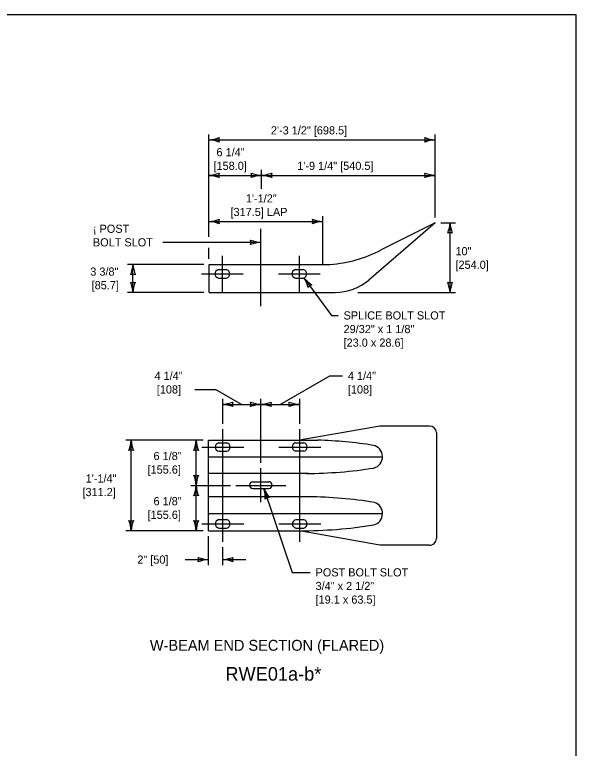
# Model space of a CAD drawing. Extents: x 49991.4 to 50021, y 49987.6 to 50011.4.
# Drawn here: x 50004.48 to 50008.61, y 50005.87 to 50011.26 of the extents above; entities that cross this region are included whole.
import ezdxf

# ---------------------------------------------------------------- set-up
doc = ezdxf.new("R2010")
doc.units = 0
for name, color, linetype in [('Level 1', 7, 'Continuous'), ('Level 2', 7, 'Continuous'), ('Level 3', 7, 'Continuous'), ('Level 5', 7, 'Continuous')]:
    doc.layers.add(name, color=color, linetype=linetype)

msp = doc.modelspace()

# ---------------------------------------------------------------- linework, layer by layer
at = {"layer": 'Level 1'}
for p, q in [((50007.577, 50009.7319), (50007.0892, 50009.3105)), ((50007.577, 50009.7319), (50007.1778, 50009.5325)), ((50005.9132, 50009.2185), (50005.9132, 50009.4265)), ((50005.9132, 50009.4265), (50006.8026, 50009.4265)), ((50005.9814, 50009.3881), (50006.0394, 50009.3881)), ((50006.548, 50009.3881), (50006.606, 50009.3881)), ((50005.9814, 50009.3255), (50006.0393, 50009.3255)), ((50006.5481, 50009.3255), (50006.606, 50009.3255)), ((50005.9132, 50009.2185), (50006.8398, 50009.2185)), ((50007.1678, 50008.2372), (50006.5772, 50008.1336)), ((50007.5344, 50008.2372), (50007.1678, 50008.2372)), ((50007.5858, 50008.1895), (50007.5858, 50007.4106)), ((50005.909, 50007.4669), (50005.909, 50008.1336)), ((50005.909, 50008.1336), (50006.7125, 50008.1336)), ((50005.9839, 50008.1141), (50006.0422, 50008.1141)), ((50006.5504, 50008.1144), (50006.609, 50008.1144)), ((50005.909, 50008.0104), (50007.1888, 50008.0104)), ((50005.9838, 50008.0516), (50006.0423, 50008.0516)), ((50006.5506, 50008.0519), (50006.5506, 50008.0519)), ((50006.6088, 50008.0519), (50006.5506, 50008.0519)), ((50006.644, 50007.8874), (50005.909, 50007.8874)), ((50006.2335, 50007.8276), (50006.3515, 50007.8276)), ((50006.2348, 50007.7776), (50006.3527, 50007.7776)), ((50006.644, 50007.7166), (50005.909, 50007.7166)), ((50005.909, 50007.5944), (50007.1888, 50007.5944)), ((50005.9839, 50007.5489), (50006.0422, 50007.5489)), ((50006.6087, 50007.5485), (50006.5507, 50007.5485)), ((50005.9838, 50007.4864), (50006.0423, 50007.4864)), ((50006.5507, 50007.4859), (50006.6087, 50007.4859)), ((50005.909, 50007.4669), (50006.5772, 50007.4669)), ((50007.1678, 50007.3609), (50006.5768, 50007.4669)), ((50007.5313, 50007.3609), (50007.1678, 50007.3609))]:
    msp.add_line(p, q, dxfattribs=at)
msp.add_lwpolyline([(50008.6146, 50011.2628), (50000.3356, 50011.2628), (50000.3356, 50000.0624), (50008.6146, 50000.0624)], close=True, dxfattribs=at)
for centre, radius, start, end in [((50006.7393, 50010.3672), 0.9429, 273.8489, 297.7135), ((50005.9883, 50009.3568), 0.0321, 102.4385, 257.5922), ((50006.0324, 50009.3568), 0.0321, 282.411, 77.5583), ((50006.555, 50009.3568), 0.0321, 102.4385, 257.5922), ((50006.5991, 50009.3568), 0.0321, 282.411, 77.5583), ((50006.83, 50009.6289), 0.4105, 271.3668, 309.1473), ((50007.5354, 50008.1867), 0.0505, 3.1941, 91.1135), ((50006.5981, 50004.7284), 3.4071, 81.1729, 88.076), ((50005.991, 50008.0828), 0.0321, 102.7122, 257.0492), ((50006.0351, 50008.0828), 0.0321, 282.9538, 77.2847), ((50006.5576, 50008.0832), 0.0321, 102.9802, 257.2893), ((50006.6018, 50008.0832), 0.0321, 282.6853, 77.0167), ((50007.103, 50008.0113), 0.0858, 285.168, 77.951), ((50006.5969, 50011.2943), 3.4071, 270.5497, 278.925), ((50006.2348, 50007.8026), 0.025, 93.1278, 270.0049), ((50006.3515, 50007.8026), 0.025, 272.7801, 89.9976), ((50006.6008, 50004.3098), 3.4071, 81.0853, 89.273), ((50007.1024, 50007.5935), 0.0864, 285.0365, 72.2425), ((50005.991, 50007.5176), 0.0321, 102.6822, 257.0198), ((50006.0351, 50007.5176), 0.0321, 282.9833, 77.3147), ((50006.5576, 50007.5172), 0.0321, 102.4078, 257.5615), ((50006.6018, 50007.5172), 0.0321, 282.4417, 77.589), ((50006.5842, 50010.874), 3.4071, 269.8825, 279.1301), ((50007.5345, 50007.4121), 0.0513, 266.5051, 358.2722)]:
    msp.add_arc(centre, radius, start, end, dxfattribs=at)
at = {"layer": 'Level 3'}
for p, q in [((50005.9104, 50009.6284), (50005.9104, 50010.3821)), ((50005.9104, 50010.3421), (50007.577, 50010.3421)), ((50007.577, 50009.7719), (50007.577, 50010.3821)), ((50006.298, 50009.9816), (50006.298, 50010.1211)), ((50005.9104, 50010.0811), (50006.298, 50010.0811)), ((50006.298, 50010.0811), (50007.577, 50010.0811)), ((50005.9104, 50009.7416), (50006.7506, 50009.7416)), ((50006.7506, 50009.4265), (50006.7506, 50009.7816)), ((50007.617, 50009.7319), (50007.7254, 50009.7319)), ((50007.6854, 50009.2185), (50007.6854, 50009.7319)), ((50005.5724, 50009.5884), (50006.2937, 50009.5884)), ((50005.9104, 50009.4665), (50005.9104, 50009.5484)), ((50005.8732, 50009.4265), (50005.3127, 50009.4265)), ((50005.3527, 50009.2185), (50005.3527, 50009.4265)), ((50006.611, 50009.327), (50006.8124, 50009.0508)), ((50005.8732, 50009.2185), (50005.3127, 50009.2185)), ((50007.007, 50009.2185), (50007.7254, 50009.2185)), ((50006.8124, 50009.0508), (50006.8621, 50009.0508)), ((50006.4353, 50008.3968), (50006.8007, 50008.6064)), ((50006.8007, 50008.6064), (50006.8938, 50008.6064)), ((50005.8079, 50008.5064), (50005.961, 50008.5064)), ((50006.1521, 50008.3968), (50005.961, 50008.5064)), ((50006.0104, 50008.4368), (50006.0104, 50008.2544)), ((50006.0104, 50008.3968), (50006.2937, 50008.3968)), ((50006.2937, 50007.9676), (50006.2937, 50008.4368)), ((50006.2937, 50008.3968), (50006.577, 50008.3968)), ((50006.577, 50008.4368), (50006.577, 50008.2544)), ((50005.869, 50008.1336), (50005.2991, 50008.1336)), ((50005.3391, 50007.4675), (50005.3391, 50008.1336)), ((50005.818, 50007.8002), (50005.818, 50008.1336)), ((50005.778, 50007.8002), (50006.0699, 50007.8002)), ((50005.818, 50007.4669), (50005.818, 50007.8002)), ((50006.3167, 50007.7776), (50006.5229, 50007.1611)), ((50005.869, 50007.4669), (50005.2991, 50007.4669)), ((50005.909, 50007.2147), (50005.909, 50007.4269)), ((50006.0104, 50007.3464), (50006.0104, 50007.2147)), ((50005.7356, 50007.2547), (50005.909, 50007.2547)), ((50006.0104, 50007.2547), (50006.1838, 50007.2547)), ((50006.5229, 50007.1611), (50006.656, 50007.1611))]:
    msp.add_line(p, q, dxfattribs=at)
for centre, radius, start, end in [((50005.8989, 50010.5749), 0.233, 272.8273, 292.0772), ((50005.9012, 50010.12), 0.2223, 67.456, 87.6395), ((50006.0386, 50010.3421), 0.0548, 162.1388, 197.8612), ((50007.5862, 50010.5643), 0.2223, 247.456, 267.6395), ((50007.4488, 50010.3421), 0.0548, 342.1388, 17.8612), ((50007.5885, 50010.1094), 0.233, 92.8273, 112.0772), ((50005.8989, 50010.3139), 0.233, 272.8273, 292.0772), ((50005.9012, 50009.859), 0.2223, 67.456, 87.6395), ((50006.0386, 50010.0811), 0.0548, 162.1388, 197.8612), ((50006.3072, 50010.3033), 0.2223, 247.456, 267.6395), ((50006.1698, 50010.0811), 0.0548, 342.1388, 17.8612), ((50006.3095, 50009.8484), 0.233, 92.8273, 112.0772), ((50006.2865, 50010.3139), 0.233, 272.8273, 292.0772), ((50006.2888, 50009.859), 0.2223, 67.456, 87.6395), ((50006.4262, 50010.0811), 0.0548, 162.1388, 197.8612), ((50007.5862, 50010.3033), 0.2223, 247.456, 267.6395), ((50007.4488, 50010.0811), 0.0548, 342.1388, 17.8612), ((50007.5885, 50009.8484), 0.233, 92.8273, 112.0772), ((50005.8989, 50009.9744), 0.233, 272.8273, 292.0772), ((50005.9012, 50009.5195), 0.2223, 67.456, 87.6395), ((50006.0386, 50009.7416), 0.0548, 162.1388, 197.8612), ((50006.7598, 50009.9638), 0.2223, 247.456, 267.6395), ((50006.6224, 50009.7416), 0.0548, 342.1388, 17.8612), ((50006.7621, 50009.5089), 0.233, 92.8273, 112.0772), ((50007.4633, 50009.7411), 0.2223, 337.456, 357.6395), ((50007.9181, 50009.7434), 0.233, 182.8273, 202.0772), ((50007.6854, 50009.6037), 0.0548, 72.1388, 107.8612), ((50006.3029, 50009.8105), 0.2223, 247.456, 267.6395), ((50006.1655, 50009.5884), 0.0548, 342.1388, 17.8612), ((50006.3052, 50009.3557), 0.233, 92.8273, 112.0772), ((50005.1306, 50009.4357), 0.2223, 337.456, 357.6395), ((50005.5854, 50009.438), 0.233, 182.8273, 202.0772), ((50005.3527, 50009.2983), 0.0548, 72.1388, 107.8612), ((50006.4261, 50009.2036), 0.2223, 13.554, 33.7375), ((50006.7922, 50009.4734), 0.233, 218.9253, 238.1751), ((50005.3527, 50009.3467), 0.0548, 252.1388, 287.8612), ((50005.12, 50009.207), 0.233, 2.8273, 22.0772), ((50005.5748, 50009.2093), 0.2223, 157.456, 177.6395), ((50006.6865, 50009.2234), 0.0548, 108.2368, 143.9591), ((50007.6854, 50009.3467), 0.0548, 252.1388, 287.8612), ((50007.4527, 50009.207), 0.233, 2.8273, 22.0772), ((50007.9075, 50009.2093), 0.2223, 157.456, 177.6395), ((50005.9989, 50008.6295), 0.233, 272.8273, 292.0772), ((50006.0012, 50008.1747), 0.2223, 67.456, 87.6395), ((50006.1386, 50008.3968), 0.0548, 162.1388, 197.8612), ((50006.3029, 50008.6189), 0.2223, 247.456, 267.6395), ((50006.1655, 50008.3968), 0.0548, 342.1388, 17.8612), ((50006.3052, 50008.1641), 0.233, 92.8273, 112.0772), ((50006.2822, 50008.6295), 0.233, 272.8273, 292.0772), ((50006.2845, 50008.1747), 0.2223, 67.456, 87.6395), ((50006.4219, 50008.3968), 0.0548, 162.1388, 197.8612), ((50006.5862, 50008.6189), 0.2223, 247.456, 267.6395), ((50006.4488, 50008.3968), 0.0548, 342.1388, 17.8612), ((50006.5885, 50008.1641), 0.233, 92.8273, 112.0772), ((50005.117, 50008.1428), 0.2223, 337.456, 357.6395), ((50005.5718, 50008.1451), 0.233, 182.8273, 202.0772), ((50005.5959, 50008.1428), 0.2223, 337.456, 357.6395), ((50006.0507, 50008.1451), 0.233, 182.8273, 202.0772), ((50005.3391, 50008.0054), 0.0548, 72.1388, 107.8612), ((50005.818, 50008.0054), 0.0548, 72.1388, 107.8612), ((50005.818, 50007.9284), 0.0548, 252.1388, 287.8612), ((50005.5853, 50007.7887), 0.233, 2.8273, 22.0772), ((50006.0401, 50007.791), 0.2223, 157.456, 177.6395), ((50005.5959, 50007.8094), 0.2223, 337.456, 357.6395), ((50006.0507, 50007.8117), 0.233, 182.8273, 202.0772), ((50006.1031, 50007.7159), 0.2223, 355.9453, 16.1288), ((50006.5338, 50007.8623), 0.233, 201.3166, 220.5665), ((50005.818, 50007.672), 0.0548, 72.1388, 107.8612), ((50006.3574, 50007.656), 0.0548, 90.6281, 126.3505), ((50005.3391, 50007.5951), 0.0548, 252.1388, 287.8612), ((50005.1064, 50007.4554), 0.233, 2.8273, 22.0772), ((50005.5612, 50007.4577), 0.2223, 157.456, 177.6395), ((50005.818, 50007.5951), 0.0548, 252.1388, 287.8612), ((50005.5853, 50007.4554), 0.233, 2.8273, 22.0772), ((50006.0401, 50007.4577), 0.2223, 157.456, 177.6395), ((50005.9182, 50007.4768), 0.2223, 247.456, 267.6395), ((50005.7808, 50007.2547), 0.0548, 342.1388, 17.8612), ((50005.9205, 50007.022), 0.233, 92.8273, 112.0772), ((50005.9989, 50007.4874), 0.233, 272.8273, 292.0772), ((50006.0012, 50007.0326), 0.2223, 67.456, 87.6395), ((50006.1386, 50007.2547), 0.0548, 162.1388, 197.8612)]:
    msp.add_arc(centre, radius, start, end, dxfattribs=at)
at = {"layer": 'Level 5'}
for p, q in [((50006.2937, 50009.1185), (50006.2937, 50009.6884)), ((50006.0104, 50009.2255), (50006.0104, 50009.4881)), ((50006.577, 50009.2255), (50006.577, 50009.4881)), ((50005.8562, 50009.3568), (50006.1645, 50009.3568)), ((50006.4229, 50009.3568), (50006.7312, 50009.3568)), ((50006.0104, 50008.2141), (50006.0104, 50007.3864)), ((50006.577, 50008.2144), (50006.577, 50007.3859)), ((50005.8589, 50008.0828), (50006.1672, 50008.0828)), ((50006.4256, 50008.0821), (50006.7338, 50008.0821)), ((50006.2937, 50007.6776), (50006.2937, 50007.9276)), ((50006.1099, 50007.8002), (50006.4764, 50007.8002)), ((50005.8589, 50007.5176), (50006.1672, 50007.5176)), ((50006.4256, 50007.5172), (50006.7338, 50007.5172))]:
    msp.add_line(p, q, dxfattribs=at)

# ---------------------------------------------------------------- texts
at = {"layer": 'Level 2'}
for s, height, p in [('2\'-3 1/2" [698.5]', 0.06, (50006.3673, 50010.3821)), ('6 1/4"', 0.06, (50005.9671, 50010.2211)), ('[158.0]', 0.06, (50005.9452, 50010.1211)), ('1\'-9 1/4" [540.5]', 0.06, (50006.5611, 50010.1211)), ('1\'-1/2"', 0.06, (50006.1833, 50009.8816)), ('[317.5] LAP', 0.06, (50006.0703, 50009.7816)), ('¡ POST', 0.06, (50005.058, 50009.6584)), ('BOLT SLOT', 0.06, (50005.058, 50009.5584)), ('10"', 0.06, (50007.7254, 50009.4932)), ('[254.0]', 0.06, (50007.7254, 50009.3932)), ('3 3/8"', 0.06, (50005.0386, 50009.3431)), ('[85.7]', 0.06, (50005.0486, 50009.2431)), ('SPLICE BOLT SLOT', 0.06, (50006.9021, 50009.0208)), ('29/32" x 1 1/8"', 0.06, (50006.9021, 50008.9208)), ('[23.0 x 28.6]', 0.06, (50006.9021, 50008.8208)), ('4 1/4"', 0.06, (50005.5111, 50008.5764)), ('4 1/4"', 0.06, (50006.9338, 50008.5764)), ('[108]', 0.06, (50005.5279, 50008.4764)), ('[108]', 0.06, (50006.9338, 50008.4764)), ('6 1/8"', 0.06, (50005.5039, 50007.987)), ('[155.6]', 0.06, (50005.4601, 50007.887)), ('1\'-1/4"', 0.06, (50005.0046, 50007.8218)), ('[311.2]', 0.06, (50004.9812, 50007.7218)), ('6 1/8"', 0.06, (50005.5039, 50007.6543)), ('[155.6]', 0.06, (50005.4601, 50007.5543)), ('2" [50]', 0.06, (50005.3845, 50007.2247)), ('POST BOLT SLOT', 0.06, (50006.696, 50007.1311)), ('3/4" x 2 1/2"', 0.06, (50006.696, 50007.0311)), ('[19.1 x 63.5]', 0.06, (50006.696, 50006.9311)), ('W-BEAM END SECTION (FLARED)', 0.08, (50005.4773, 50006.5844)), ('RWE01a-b*', 0.1, (50006.0328, 50006.3644))]:
    msp.add_text(s, height=height, dxfattribs=at).set_placement(p)

doc.saveas('drawing.dxf')
